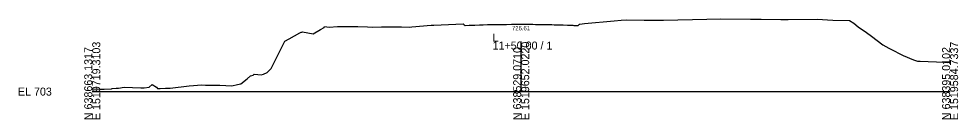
# Model space of a CAD drawing. Extents: x -26 to 3903, y -10 to 9531.
# Drawn here: x -25.7 to 302.8, y 1490.3 to 1525.5 of the extents above; entities that cross this region are included whole.
import ezdxf

# ---------------------------------------------------------------- set-up
doc = ezdxf.new("R2010")
doc.units = 0
for name, color, linetype in [('Default', 7, 'Continuous'), ('Exist Cross Section Cell', 7, 'Continuous'), ('Exist XS Center Line Elevation Label', 7, 'Continuous'), ('Exist XS Ground Line', 7, 'Continuous')]:
    doc.layers.add(name, color=color, linetype=linetype)

msp = doc.modelspace()

# ---------------------------------------------------------------- linework, layer by layer
at = {"layer": 'Exist Cross Section Cell'}
for p, q in [((150, 1500), (150, 1517.53)), ((0, 1500), (150, 1500)), ((150, 1500), (300, 1500))]:
    msp.add_line(p, q, dxfattribs=at)
at = {"layer": 'Exist XS Ground Line'}
msp.add_lwpolyline([(0, 1500.91), (2.88, 1500.87), (3.76, 1500.84), (4.13, 1500.85), (6.78, 1501.01), (6.96, 1501.03), (8.41, 1501.16), (9.2, 1501.24), (11.12, 1501.59), (17.01, 1501.27), (18.2, 1501.29), (19.93, 1501.58), (20.95, 1502.52), (22.52, 1501.58), (22.8, 1501.11), (23.73, 1501.13), (25.58, 1501.17), (27.21, 1501.21), (33.93, 1502.02), (38.33, 1502.33), (39.64, 1502.28), (42.7, 1502.29), (44.23, 1502.26), (44.47, 1502.26), (44.67, 1502.28), (48.87, 1502.01), (50.85, 1502.44), (51.97, 1502.77), (54.2, 1504.5), (55.38, 1505.51), (56.23, 1505.77), (56.65, 1506.08), (57.9, 1506.04), (59.02, 1505.84), (59.85, 1506.06), (61.12, 1506.74), (62.54, 1508.07), (64.65, 1512.32), (67.3, 1517.61), (68.82, 1518.47), (72.58, 1520.61), (73.03, 1520.87), (73.26, 1520.88), (73.53, 1520.89), (77.23, 1520.18), (79.86, 1521.81), (81.15, 1522.46), (81.26, 1522.76), (82.83, 1522.58), (85.78, 1522.75), (87.55, 1522.78), (88.6, 1522.77), (89.49, 1522.81), (90.24, 1522.79), (92.83, 1522.75), (96.25, 1522.7), (98.01, 1522.61), (101.2, 1522.72), (108.18, 1522.67), (110.86, 1522.61), (111.72, 1522.66), (118.5, 1523.25), (118.77, 1523.28), (119.4, 1523.3), (129.72, 1523.7), (130.06, 1523.44), (130.38, 1523.19), (131.83, 1523.27), (132.19, 1523.29), (132.99, 1523.3), (133.18, 1523.31), (133.8, 1523.32), (135.46, 1523.37), (136.73, 1523.41), (138.27, 1523.45), (138.69, 1523.46), (139.7, 1523.5), (140.19, 1523.5), (141.05, 1523.5), (142.86, 1523.53), (143.85, 1523.55), (144.82, 1523.56), (146.62, 1523.58), (148.45, 1523.6), (149.42, 1523.6), (149.66, 1523.61), (149.87, 1523.62), (150.93, 1523.61), (152.25, 1523.59), (154.09, 1523.57), (155.02, 1523.56), (155.97, 1523.54), (157.82, 1523.5), (159.19, 1523.48), (159.97, 1523.47), (160.03, 1523.47), (160.67, 1523.45), (161.53, 1523.43), (162.78, 1523.4), (163.4, 1523.38), (164.63, 1523.34), (166.22, 1523.29), (166.49, 1523.28), (167.81, 1523.23), (168.05, 1523.22), (168.46, 1523.21), (169.89, 1523.18), (170.39, 1523.6), (170.47, 1523.67), (172.18, 1523.81), (182.53, 1524.81), (184.92, 1525.05), (186.99, 1525.17), (192.97, 1525.04), (197.35, 1525.01), (199.74, 1525.06), (214.97, 1525.36), (219.71, 1525.52), (230.25, 1525.39), (233.92, 1525.38), (240.75, 1525.28), (242.08, 1525.22), (243.41, 1525.28), (253.54, 1525.36), (259.02, 1525.03), (264.87, 1524.88), (266.32, 1523.99), (267.83, 1522.64), (270.75, 1520.75), (272.53, 1519.39), (276.45, 1516.38), (278.57, 1515.27), (279.08, 1514.98), (283.63, 1512.68), (287.23, 1511.13), (288.56, 1510.71), (289.49, 1510.64), (298.08, 1510.3), (299.22, 1510.14), (299.43, 1510.3), (300, 1510.26)], dxfattribs=at)

# ---------------------------------------------------------------- texts
at = {"layer": 'Default'}
msp.add_text('-', height=0.0001, dxfattribs=at).set_placement((0, 1500))
at = {"layer": 'Exist Cross Section Cell'}
for s, p in [('L', (140, 1517.53)), ('11+50.00 / 1', (140, 1514.73)), ('EL 703', (-26, 1498.6))]:
    msp.add_text(s, height=2.8, dxfattribs=at).set_placement(p)
for s, p in [('N 638663.1317', (0, 1490)), ('E 1519719.3103', (2.8, 1490)), ('N 638529.0710', (150, 1490)), ('E 1519652.0220', (152.8, 1490)), ('N 638395.0102', (300, 1490)), ('E 1519584.7337', (302.8, 1490))]:
    msp.add_text(s, height=2.8, rotation=90, dxfattribs=at).set_placement(p)
at = {"layer": 'Exist XS Center Line Elevation Label'}
msp.add_text('726.61', height=1.5, rotation=0.8401, dxfattribs=at).set_placement((146.79, 1521.41))

doc.saveas('drawing.dxf')
